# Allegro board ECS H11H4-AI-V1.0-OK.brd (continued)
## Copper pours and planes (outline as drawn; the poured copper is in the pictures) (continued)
N32242493 on TOP (solid shape): 48.29,32.15 48.29,31.31 47.19,30.22 47.04,30.22 47.01,30.23 46.99,30.27 46.99,31.04 46.99,31.34 47.45,31.79 47.45,32.2 47.57,32.33 48.11,32.33
N32957662 on TOP (solid shape): 40.74,159.4 41.58,159.4 41.63,159.35 41.63,159.2 41.55,159.12 40.89,159.12 40.69,158.92 40.69,158.41 40.62,158.34 39.98,158.34 39.85,158.21 39.85,156.94 41.5,155.29 41.5,152.43 41.44,152.37 37.93,152.37 37.62,152.67 37.62,156.25 38.76,157.4 38.76,159 38.84,159.07 39.7,159.07 39.8,159.17 39.8,159.45 39.85,159.5 40.64,159.5
N32957662 on BOTTOM (solid shape): 41.63,159.35 41.63,159.2 41.55,159.12 40.89,159.12 40.69,158.92 40.69,158.29 40.59,158.18 39.98,158.18 39.85,158.06 39.85,156.94 41.5,155.29 41.5,152.43 41.44,152.37 37.93,152.37 37.62,152.67 37.62,156.25 38.76,157.4 38.76,158.87 38.84,158.95 39.75,158.95 39.85,159.05 39.85,159.35 39.9,159.4 41.58,159.4
N32978550 on TOP (solid shape): 43.89,164.3 43.89,164.28 44.06,164.11 44.06,161.72 44.62,161.17 45.5,161.17 45.7,160.98 45.7,159.9 45.56,159.76 42.37,159.76 42.14,159.53 41.63,159.53 40.84,159.53 40.74,159.63 39.8,159.63 39.73,159.63 39.62,159.53 39.62,159.25 39.57,159.2 38.79,159.2 38.75,159.22 38.74,159.25 38.74,159.43 38.66,159.5 37.87,159.5 37.8,159.58 37.8,159.73 37.87,159.81 38.66,159.81 38.74,159.89 38.74,160.19 38.81,160.27 39.95,160.27 40.03,160.34 40.03,161.57 39.96,161.64 39.96,164.28 40.27,164.59 43.59,164.59
N33306621 on TOP (solid shape): 33.88,16.07 33.88,14.8 33.76,14.67 30.96,14.67 30.58,15.06 30.58,16.07 30.96,16.45 33.5,16.45

Small or netless copper shapes (teardrops, artwork), in the pictures only: 221 on TOP, 4 on BOTTOM, 2 on PWR

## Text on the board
Ref Des/Silkscreen Top: A5 | D | R | B | C | A | A1 | E | N | A3 | A2 | F | H | P | G | I | J | K | L | O | 15-KV7-011000 | H11H4-AI V:1.0
User.14: 15-KV7-011000 | H11H4-AI V:1.0 TOP
User.15: 15-KV7-011000 | H11H4-AI V:1.0 BOT
User.45: +VCCIO | GND | SYX196D_P10 | VSA_PH | 59.1 | +V1P0A | P95_PH | +1V05_SA | +VIN_SA | PHASE1_A | UP1740P_PHASE | PHASE2_A | 6182_PH1 | +VIN_CPU | 6182_PH2 | PHASE3_A | PHASE2_B | PHASE1_B | +12V_4P | 6182_+VIN | FIGURE | SIZE | 10.0 | 12.0 | 14.0 | 16.0 | 20.0 | 26.0 | 28.0 | 30.0 | 32.0 | 33.0 | 36.0 | 37.0 | 40.0 | 42.0 | 44.0 | 48.0 | 52.0 | 54.0 | 55.0 | 56.0 | 60.0 | 72.0 | 92.0 | 128.0 | 93.0 | 96.0 | 124.0 | 152.0 | 156.0 | 160.0 | 44.0x40.0 | 64.0x36.0 | 70.0x52.0 | 78.0x60.0 | 90.0x72.0 | 108.0x36.0 | 96.0x47.0 | DRILL CHART: TOP to BOTTOM | ALL UNITS ARE IN MILS | TOLERANCE | +3.0/-3.0 | +4.0/-4.0 | PLATED | NON-PLATED | QTY | 747 | 3034 | 48 | 12 | 74 | 578 | 184 | 14 | 25 | 2 | 16 | 8 | 159 | 15 | 1 | 6 | 4 | 5 | 21 | 3 | 13 | +5VSB | AUGND | +12V | +VCC3 | +3VSB | +VDIMM | +VCC
